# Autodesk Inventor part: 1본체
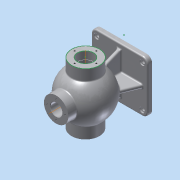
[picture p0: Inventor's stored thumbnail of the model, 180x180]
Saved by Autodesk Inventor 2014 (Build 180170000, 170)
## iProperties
Created: 2017-01
Part Number: 1본체
Material: Aluminum 6061
Document SubType Name: Modeling
Designer: ksu
Density: 2.71 g/cm^3
Appearance: Aluminum - Flat
Author: ksu
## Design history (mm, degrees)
sketch "Sketch1"
  geometry: L1 (-62.5, 57.5)-(62.5, 57.5); L2 (62.5, 57.5)-(62.5, -57.5); L3 (62.5, -57.5)-(-62.5, -57.5); L4 (-62.5, -57.5)-(-62.5, 57.5); L5 (-62.5, 57.5)-(62.5, -57.5); L6 (62.5, 57.5)-(-62.5, -57.5); 1 further point
  constraints: 12 end point, 2 midpoint, 2 parallel, 1 horizontal, 1 perpendicular
  dimensions: "d0" = 125 distance of L2.end L3.end; "d1" = 115 distance of L1.end L2.end
extrude "Extrusion1" new body sketch "Sketch1" distance "d2" = 10; taper "d3" = 0 deg
sketch "Sketch2"
  geometry: L1 (0, 0)-(0, 85); L2 (-24.205, 37.85)-(24.205, 132.15); A1 r 53 centre (0, 85) between (-24.205, 37.85) and (24.205, 132.15)
  constraints: 4 end point, 2 point on circle, 1 centre point, 1 coincident, 1 midpoint, 1 vertical
  dimensions: "d4" = 85 distance of L1.start L1.end; "d5" = 106 diameter of A1
revolve "Revolution1" sketch "Sketch2" stored, may be unused: angle "d6" = 90 deg
workplane "Work Plane1"
sketch "Sketch3"
  geometry: C1 r 27 at (0, 0); 1 further point
  constraints: 1 centre point, 1 coincident
  dimensions: "d8" = 54 diameter of C1
extrude "Extrusion2" join sketch "Sketch3" distance "d9" = 65; taper "d10" = 0 deg
sketch "Sketch4"
  geometry: L1 (0, 0)-(0, 85); C1 r 31 at (0, 85)
  constraints: 2 end point, 1 centre point, 1 coincident, 1 vertical
  dimensions: "d11" = 85 distance of L1.start L1.end; "d12" = 62 diameter of C1
extrude "Extrusion3" join sketch "Sketch4" stored distance "d13" = 136; taper "d14" = 0 deg
sketch "Sketch5"
  geometry: L1 (-52.5, 10)-(-27.325, 72.31); L2 (-27.325, 72.31)-(0, 72.31); L3 (27.325, 72.31)-(0, 72.31); L4 (52.5, 10)-(27.325, 72.31); L5 (-52.5, 10)-(52.5, 10); 2 further points
  constraints: 10 end point
extrude "Extrusion4" join sketch "Sketch5" stored distance "d17" = 8; taper "d18" = 0 deg
sketch "Sketch6"
  geometry: L1 (57.5, 10)-(-57.5, 10) reference; L2 (-57.5, 10)-(-47.5, 10); L3 (-47.5, 10)-(-16.493, 86.744); L4 (-16.493, 86.744)-(0, 86.744); L5 (-47.5, 10)-(0, 10); L6 (47.5, 10)-(16.493, 86.744); L7 (16.493, 86.744)-(0, 86.744); L8 (47.5, 10)-(0, 10); 1 further point
  constraints: 14 end point, 1 midpoint, 1 parallel, 1 point on line
  dimensions: "d19" = 10 distance of L1.end L2.end; "d20" = 112 deg angle of L2 L3
extrude "Extrusion5" join sketch "Sketch6" stored distance "d21" = 8; taper "d22" = 0 deg
sketch "Sketch7"
  geometry: L1 (0, 0)-(0, 85); L2 (7.89, 42.73)-(-7.89, 127.27); A1 r 43 centre (0, 85) between (7.89, 42.73) and (-7.89, 127.27)
  constraints: 4 end point, 2 point on circle, 1 centre point, 1 coincident, 1 midpoint, 1 vertical
  dimensions: "d23" = 85 distance of L1.start L1.end; "d24" = 86 diameter of A1
revolve "Revolution2" sketch "Sketch7" stored, may be unused: angle "d25" = 90 deg
sketch "Sketch8"
  geometry: C1 r 31 at (0, 0) reference; C2 r 17.5 at (0, 0); 1 further point
  constraints: 1 centre point, 1 coincident
  dimensions: "d26" = 35 diameter of C2
extrude "Extrusion6" cut sketch "Sketch8" stored distance "d27" = 8; taper "d28" = 0 deg
sketch "Sketch9"
  geometry: C1 r 27 at (0, 0) reference; C2 r 13 at (0, 0)
  constraints: 1 centre point, 1 coincident
  dimensions: "d29" = 26 diameter of C2
extrude "Extrusion7" cut sketch "Sketch9" distance "d30" = 40; taper "d31" = 0 deg
sketch "Sketch10"
  geometry: 1 further point
sketch "Sketch11"
  geometry: L1 (68, 102.5)-(68, 67.5) reference; L2 (68, 85)-(52, 85); L3 (52, 85)-(52, 103.5); L4 (52, 103.5)-(50.25, 103.5); L5 (50.25, 103.5)-(50.25, 85); L6 (52, 85)-(50.25, 85); 1 further point
  constraints: 10 end point, 3 perpendicular, 1 midpoint, 1 parallel
  dimensions: "d32" = 16 distance of L2.start L2.end; "d33" = 18.5 distance of L2.end L3.end; "d34" = 1.75 distance of L3.end L4.end
revolve "Revolution3" sketch "Sketch11" stored, may be unused: angle "d36" = 90 deg
sketch "Sketch13"
  geometry: 1 further point
workplane "Work Plane2"
sketch "Sketch15"
  geometry: 1 further point
sketch "Sketch16"
  geometry: C1 r 17.5 at (0, 0) reference; C2 r 31 at (0, 0) reference; 1 further point
sketch "Sketch17"
  geometry: L1 (0, 0)-(0, 24); C1 r 31 at (0, 0) reference; 2 further points
  constraints: 2 end point, 1 coincident, 1 vertical
  dimensions: "d42" = 24 distance of L1.start L1.end
hole "Hole1" sketch "Sketch17" at (0, 24) diameter "d43" = 3.459; stored, may be unused: countersink angle "d47" = 90 deg, drill point angle "d49" = 118 deg; dims "d44" = 16, "d45" = 4, "d46" = 2, "d48" = 19
workaxis "Work Axis1"
pattern_circular "Circular Pattern1" dims angle "d51" = 360 deg
sketch "Sketch18"
  geometry: L1 (0, 0)-(0, 22.5); C1 r 31 at (0, 0) reference; 2 further points
  constraints: 2 end point, 1 coincident, 1 vertical
  dimensions: "d53" = 22.5 distance of L1.start L1.end
hole "Hole2" sketch "Sketch18" at (0, 22.5) diameter "d54" = 3.459; stored, may be unused: countersink angle "d58" = 90 deg, drill point angle "d60" = 118 deg; dims "d55" = 12, "d56" = 4, "d57" = 2, "d59" = 15
pattern_circular "Circular Pattern2" dims angle "d62" = 360 deg
sketch "Sketch19"
  geometry: L1 (0, 0)-(0, 20); C1 r 27 at (0, 0) reference; 1 further point
  constraints: 2 end point, 1 coincident, 1 vertical
  dimensions: "d64" = 20 distance of L1.start L1.end
hole "Hole3" sketch "Sketch19" at (0, 20) diameter "d65" = 3.459; stored, may be unused: countersink angle "d69" = 90 deg, drill point angle "d71" = 118 deg; dims "d66" = 9, "d67" = 4, "d68" = 2, "d70" = 11
workaxis "Work Axis2"
pattern_circular "Circular Pattern3" dims angle "d73" = 360 deg
sketch "Sketch20"
  geometry: L1 (-50.5, -45.5)-(50.5, -45.5); L2 (50.5, -45.5)-(50.5, 45.5); L3 (50.5, 45.5)-(-50.5, 45.5); L4 (-50.5, 45.5)-(-50.5, -45.5); L5 (-50.5, -45.5)-(50.5, 45.5); L6 (50.5, -45.5)-(-50.5, 45.5); 5 further points
  constraints: 12 end point, 4 coincident, 2 midpoint, 2 parallel, 1 horizontal, 1 perpendicular
  dimensions: "d75" = 101 distance of L3.end L2.end; "d76" = 91 distance of L2.end L1.end
hole "Hole4" sketch "Sketch20" at (-50.5, 45.5), (-50.5, -45.5), (50.5, -45.5), (50.5, 45.5) diameter "d77" = 8; stored, may be unused: countersink angle "d81" = 90 deg, drill point angle "d83" = 118 deg; dims "d78" = 9, "d79" = 12, "d80" = 3, "d82" = 10
fillet "Fillet1" dims "d84" = 12
fillet "Fillet2" dims "d85" = 3
fillet "Fillet3" dims "d86" = 3
chamfer "Chamfer1" distance "d87" = 1; stored, may be unused: second distance "d88" = 2, angle "d89" = 45 deg
workplane "Work Plane3"
sketch "Sketch21"
  geometry: L1 (27, 150)-(-27, 150) reference; L2 (-20.739, 143.002)-(20.739, 143.002); L3 (20.739, 143.002)-(20.739, 136.998); L4 (20.739, 136.998)-(-20.739, 136.998); L5 (-20.739, 136.998)-(-20.739, 143.002); L6 (0, 150)-(0, 140); L7 (-20.739, 140)-(20.739, 140); L8 (0, 143.002)-(0, 136.998); 2 further points
  constraints: 6 end point, 6 midpoint, 1 parallel, 2 other
  dimensions: "d91" = 10 distance of L6.start L6.end
emboss "Emboss2" sketch "Sketch21" dims "d92" = 0.5, "d93" = 0
fillet "Fillet4" dims "d94" = 3
body "Solid1"
other parameters: "d7" = 85
